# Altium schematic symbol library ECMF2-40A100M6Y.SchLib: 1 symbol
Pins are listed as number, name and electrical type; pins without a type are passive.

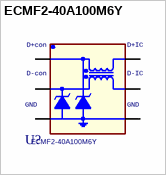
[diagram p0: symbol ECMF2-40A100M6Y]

## ECMF2-40A100M6Y
designator U?
footprint ST_QFN50P140x135x75-6L
pins: 1 D+, 2 D-, 3 GND1, 4 GND2, 5 D-1, 6 D+1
